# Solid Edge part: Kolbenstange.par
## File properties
Username: bmolnar
Dokumentum tartalom típus: 0
Author: bmolnar
Last saved by: bmolnar
Revision: 93
Sűrűség: 0,000 kg/m^3
Pontosság: 0,990
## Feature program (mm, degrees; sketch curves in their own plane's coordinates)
base feature "unnamed BaseFeature 1"
sketch for "unnamed Protrusion 1" plane through (23.5, 0, 0) normal (1, 0, 0) x-axis (0, -1, 0)
  circle centre (0, 0) radius 12.5
extrude "unnamed Protrusion 1" add finite 7 along +normal
thread "Menet_1"  ThreadDepth = 15 mm
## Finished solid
Body 1: solid body, 15 faces, 21 edges, 8 vertices.
  Faces by surface: plane 8, cylinder 4, cone 2, torus 1
  Edges by curve: circle 11, line 6, ellipse 2, intersection 2
Bounding box of the edges (mm; curved faces can reach further): 275.500 x 25.000 x 25.000, from (-245, -12.5, -12.5) to (30.5, 12.5, 12.5).
Cylindrical faces by radius (mm): R2.4585 x2, R5 x1, R12.5 x1
Conical faces (half-angle, radius in mm at the cone's reference point): 45 deg R2.8085 x1, 59 deg R1.2292 x1
Toroidal faces (ring radius, tube radius in mm): R3.8 r1.2 x1
Planar faces by outward normal: +x 1, +z 1, -x 3, -z 1, oblique 2
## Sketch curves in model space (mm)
circle centre (23.5, 0, 0) radius 12.5
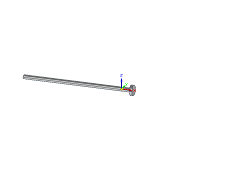
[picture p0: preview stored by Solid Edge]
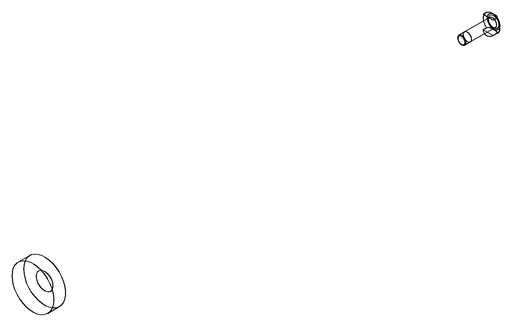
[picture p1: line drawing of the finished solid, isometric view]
